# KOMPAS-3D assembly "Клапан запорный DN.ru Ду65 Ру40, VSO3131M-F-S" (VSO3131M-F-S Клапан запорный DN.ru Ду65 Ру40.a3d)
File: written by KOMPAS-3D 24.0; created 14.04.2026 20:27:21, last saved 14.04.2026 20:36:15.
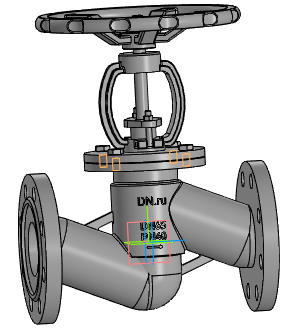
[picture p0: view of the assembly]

Document properties: Автор: R2D2; Полное имя файла: E:\Работа\Зайцев\VSO3131M-F-S Клапан запорный DN.ru Ду15-100 Ру40\DN65\исходные материалы\VSO3131M-F-S Клапан запорный DN.ru Ду65 Ру40.a3d

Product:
- Component [detail]: Корпус  | qty 1  | pos. 1  | Масса: 6.9; Автор: R2D2; source file: Корпус.m3d
- Component [detail]: Клапан запорный DN.ru Ду65 Ру16  | designation VSO1121M-F-S  | qty 1  | pos. 2  | Масса: 19.42; Раздел спецификации: Прочие изделия; Примечание: D090-01948; Автор: R2D2; source file: 2.m3d
- Component [standard]: Hexagon head screw ISO 4017 - М10 x 20  | qty 4  | Масса: 0.023019; Раздел спецификации: Стандартные изделия; Рассекать на разрезах: no
- Part/product: Клапан запорный DN.ru Ду65 Ру40  | designation VSO3131M-F-S
    Масса: 17.64
    Раздел спецификации: Прочие изделия
    Примечание: D090-02143

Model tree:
1. Массив по концентрической сетке:1  (with: Грань.Элемент вращения:2, Грань.Операция без истории:1)  (labels: Грань.Элемент выдавливания:9.Экземпляр ( 1, 2 ))  (4 pattern instances)
     Шаг 2 = 360

Expressions: D090-01948
Referenced files in E:\Работа\Зайцев\VSO3131M-F-S Клапан запорный DN.ru Ду15-100 Ру40\DN65\исходные материалы\: Корпус.m3d, 2.m3d
Referenced files in C:\Program Files\ASCON\KOMPAS-3D v24\Libs\PolynomLib\DATA\vault\Methods\Kompas\3D\: PLib_Bolt_1_ISO_1100.m3d
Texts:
  VSO1121M-F-S
  Hexagon head screw
  BOSimple***PART:c031cb5e-65ec-2f83-1ced-75228c8ad34f***PART:A259_7B16EF33AB1642D2[16;1,5;20;10;-;Undefined]
  Программные изделия  и базы данных
  VSO3131M-F-S
  VSO1121M-F-S Клапан запорный DN.ru Ду65 Ру16
  Hexagon head screw ISO 4017 - М10 x 20 (1)
  hole1
  hole2
  Ось Y.Начало координат
  Плоскость XY.Начало координат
